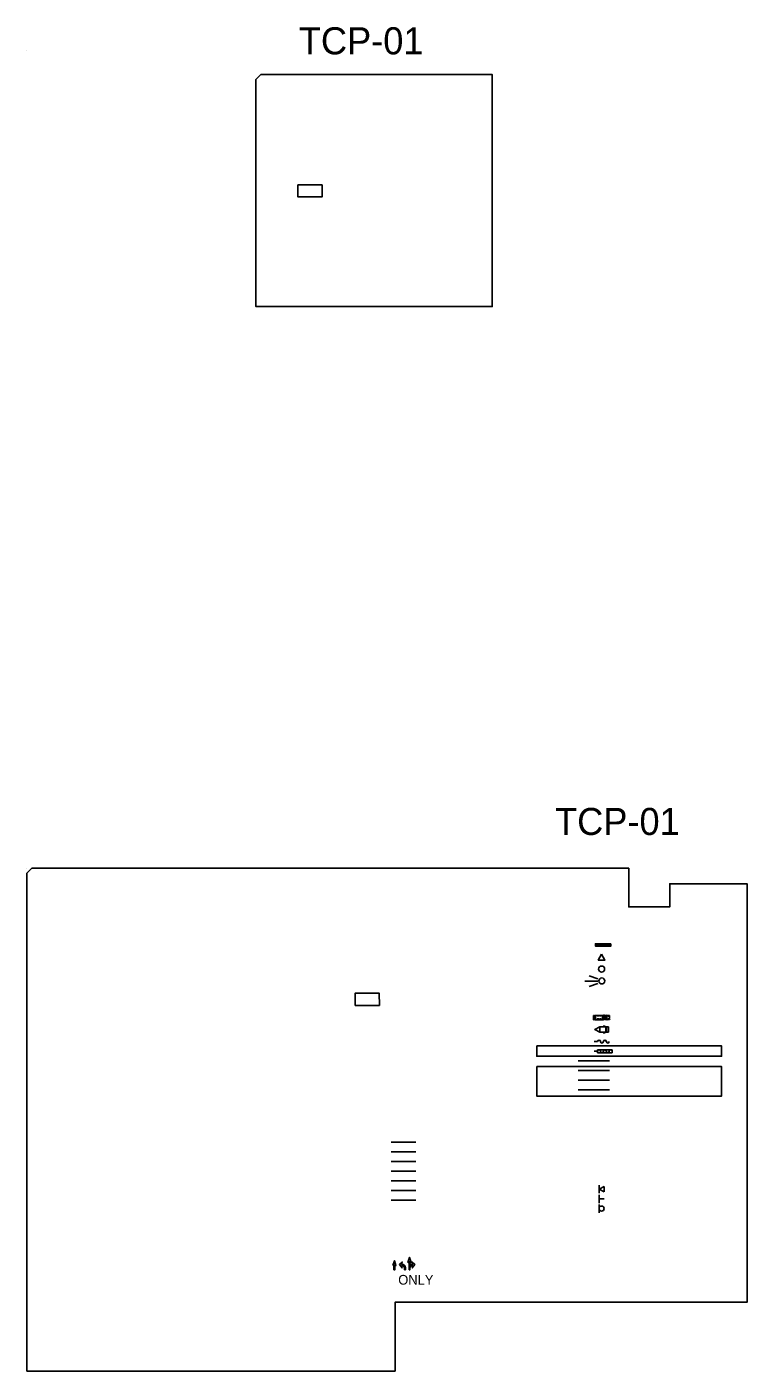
# Model space of a CAD drawing. Extents: x 2486454 to 2490507, y 369321 to 372999.
# Drawn here: x 2489017 to 2490507, y 370218 to 372999 of the extents above; entities that cross this region are included whole.
import ezdxf

# ---------------------------------------------------------------- set-up
doc = ezdxf.new("R2010")
doc.units = 0
for name, color, linetype in [('DEV BORDER CELL', 7, 'Continuous'), ('DEV CRASH CUSHION CELL', 7, 'Continuous'), ('Scratch_Level_3', 7, 'Continuous'), ('TC CONSTRUCTION PROPOSED ROADWAY SHADE', 7, 'Continuous'), ('TC DEV ATTENUATOR', 7, 'Continuous'), ('TC DEV ATTENUATOR TRUCK MOUNTED', 7, 'Continuous'), ('TC DEV BARRICADE', 7, 'Continuous'), ('TC DEV BARRIER PCB (ANCHORED)', 7, 'Continuous'), ('TC DEV BARRIER PCB (ANCHORED) RESET', 7, 'Continuous'), ('TC DEV BARRIER PCB (UN-ANCHORED)', 7, 'Continuous'), ('TC DEV BARRIER PCB (UN-ANCHORED) RESET', 7, 'Continuous'), ('TC DEV CMS', 7, 'Continuous'), ('TC DEV CONE', 7, 'Continuous'), ('TC DEV DRUM', 7, 'Continuous'), ('TC DEV SIGN', 7, 'Continuous'), ('TC DEV SIGN ARROW BOARD YELLOW', 7, 'Continuous'), ('TC PM CENTER DOUBLE 6 Y', 7, 'Continuous'), ('TC PM CHARACTER', 7, 'Continuous'), ('TC PM EDGELINE 6 W P6', 7, 'Continuous'), ('TC PM EDGELINE 6 Y P7', 7, 'Continuous'), ('TC PM GORELINE 12 W PS', 7, 'Continuous'), ('TC PM MINISKIP 3-9 6 W PK', 7, 'Continuous'), ('TC PM SKIP 6 W PJ', 7, 'Continuous'), ('TC PM STOP BAR 24 W P2', 7, 'Continuous'), ('TC PM SYMBOL', 7, 'Continuous'), ('TC SHEET LAYOUT SHAPE', 7, 'Continuous')]:
    doc.layers.add(name, color=color, linetype=linetype)

msp = doc.modelspace()

# ---------------------------------------------------------------- linework, layer by layer
at = {"layer": 'DEV BORDER CELL'}
for points in [[(2489627.4, 372671.9), (2489577.4, 372671.9), (2489577.4, 372646.9), (2489627.4, 372646.9)], [(2489745.7, 370999.8), (2489695.7, 370999.8), (2489695.8, 370974.8), (2489745.8, 370974.8)]]:
    msp.add_lwpolyline(points, close=True, dxfattribs=at)
at = {"layer": 'DEV CRASH CUSHION CELL'}
msp.add_line((2490189.8, 370879.8), (2490197.3, 370879.8), dxfattribs=at)
msp.add_lwpolyline([(2490197.3, 370882.8), (2490227.3, 370882.8), (2490227.3, 370876.8), (2490197.3, 370876.8)], close=True, dxfattribs=at)
for centre, start, end in [((2490200.3, 370879.8), 0, 180), ((2490212.3, 370879.8), 0, 180), ((2490224.3, 370879.8), 0, 180), ((2490206.3, 370879.8), 180, 0), ((2490218.3, 370879.8), 180, 0)]:
    msp.add_arc(centre, 3, start, end, dxfattribs=at)
at = {"layer": 'Scratch_Level_3'}
for p, q in [((2489016.6, 372950.1), (2489016.6, 372950.1)), ((2489016.6, 371258.3), (2489016.6, 371258.3))]:
    msp.add_line(p, q, dxfattribs=at)
for points in [[(2490071.4, 370890.8), (2490453.8, 370890.8), (2490453.8, 370869.7), (2490071.4, 370869.7)], [(2490071.4, 370848.2), (2490453.8, 370848.2), (2490453.8, 370787.2), (2490071.4, 370787.2)]]:
    msp.add_lwpolyline(points, close=True, dxfattribs=at)
at = {"layer": 'TC CONSTRUCTION PROPOSED ROADWAY SHADE'}
for points in [[(2489577.4, 372671.9), (2489627.4, 372671.9), (2489627.4, 372646.9), (2489577.4, 372646.9)], [(2489695.7, 370999.8), (2489745.7, 370999.8), (2489745.8, 370974.8), (2489695.8, 370974.8)]]:
    msp.add_lwpolyline(points, close=True, dxfattribs=at)
at = {"layer": 'TC DEV ATTENUATOR'}
msp.add_line((2490189.8, 370899.8), (2490197.3, 370899.8), dxfattribs=at)
for centre, radius, start, end in [((2490200.3, 370899.8), 3.03, 359.9999, 179.9999), ((2490206.3, 370899.8), 2.97, 179.9999, 359.9999), ((2490212.3, 370899.8), 3, 359.9999, 179.9999), ((2490218.3, 370899.8), 2.97, 179.9999, 359.9999)]:
    msp.add_arc(centre, radius, start, end, dxfattribs=at)
at = {"layer": 'TC DEV ATTENUATOR TRUCK MOUNTED'}
for p, q in [((2490188.8, 370945.2), (2490188.8, 370954.1)), ((2490188.8, 370954.1), (2490188.8, 370952.4)), ((2490188.8, 370954.1), (2490188.8, 370952.4)), ((2490188.8, 370954.1), (2490188.8, 370952.4)), ((2490188.8, 370954.1), (2490188.8, 370952.4)), ((2490188.8, 370952.4), (2490188.8, 370954.1)), ((2490188.8, 370954.1), (2490190.3, 370954.1)), ((2490190.3, 370954.1), (2490188.8, 370952.4)), ((2490188.8, 370951), (2490191.6, 370954.1)), ((2490192.8, 370954.1), (2490188.8, 370949.6)), ((2490188.8, 370949.6), (2490188.8, 370951)), ((2490188.8, 370949.6), (2490192.8, 370945.2)), ((2490188.8, 370948.3), (2490188.8, 370949.6)), ((2490191.6, 370945.2), (2490188.8, 370948.3)), ((2490188.8, 370946.9), (2490188.8, 370945.2)), ((2490190.3, 370945.2), (2490188.8, 370946.9)), ((2490188.8, 370945.2), (2490190.3, 370945.2)), ((2490190.1, 370949.6), (2490192.8, 370952.7)), ((2490192.8, 370946.6), (2490190.1, 370949.6)), ((2490192.8, 370951.3), (2490191.3, 370949.6)), ((2490191.3, 370949.6), (2490192.8, 370948)), ((2490191.6, 370954.1), (2490192.8, 370954.1)), ((2490192.8, 370945.2), (2490191.6, 370945.2)), ((2490192.7, 370954.1), (2490209.3, 370954.1)), ((2490192.8, 370945.2), (2490192.8, 370954.1)), ((2490192.8, 370952.7), (2490192.8, 370951.3)), ((2490192.8, 370948), (2490192.8, 370946.6)), ((2490192.8, 370945.2), (2490209.4, 370945.2)), ((2490196.1, 370954.1), (2490196.1, 370952.8)), ((2490196.1, 370952.8), (2490199.9, 370952.8)), ((2490196.1, 370946.6), (2490199.9, 370946.6)), ((2490196.1, 370946.6), (2490196.1, 370945.2)), ((2490199.9, 370954.1), (2490199.9, 370952.8)), ((2490199.9, 370946.6), (2490199.9, 370945.2)), ((2490201.1, 370954.2), (2490201.1, 370952.8)), ((2490201.1, 370952.8), (2490204.8, 370952.8)), ((2490201.1, 370946.6), (2490204.8, 370946.6)), ((2490201.1, 370946.6), (2490201.1, 370945.2)), ((2490204.8, 370954.2), (2490204.8, 370952.8)), ((2490204.8, 370946.6), (2490204.8, 370945.2)), ((2490207.1, 370954.1), (2490207.1, 370945.2)), ((2490209.3, 370954.1), (2490209.4, 370945.2)), ((2490211.9, 370954.1), (2490214.1, 370954.3)), ((2490211.9, 370945.5), (2490214.4, 370945.2)), ((2490216.1, 370953.5), (2490214.1, 370954.3)), ((2490216.3, 370945.8), (2490214.4, 370945.2)), ((2490216.1, 370953.6), (2490216.3, 370945.8)), ((2490216.1, 370953.5), (2490222, 370951.9)), ((2490216.3, 370945.8), (2490222.1, 370947.4)), ((2490222, 370951.9), (2490222.1, 370947.4))]:
    msp.add_line(p, q, dxfattribs=at)
for centre, radius, start, end in [((2490197.2, 370949.7), 15.3, 343.8365, 16.7472), ((2490205.8, 370949.5), 9.52, 333.4445, 30.0214), ((2490220.5, 370952.7), 1.61, 331.8365, 28.0763), ((2490220.7, 370946.6), 1.61, 331.8365, 28.0763)]:
    msp.add_arc(centre, radius, start, end, dxfattribs=at)
for centre, major_axis, ratio, start_param, end_param in [((2490210.6, 370954.1), (1.27, 0), 0.269913, 0, 3.141593), ((2490210.7, 370945.5), (1.26, 0), 0.27366, 3.141593, 6.283185), ((2490219, 370953.5), (2.91, -0.04), 0.2034, 0, 3.141593), ((2490219.2, 370945.8), (2.91, 0.03), 0.2034, 3.141593, 6.283185)]:
    msp.add_ellipse(centre, major_axis=major_axis, ratio=ratio, start_param=start_param, end_param=end_param, dxfattribs=at)
at = {"layer": 'TC DEV BARRICADE'}
for p, q in [((2490196.8, 371102.3), (2490192.8, 371097.3)), ((2490192.8, 371097.3), (2490192.8, 371102.3)), ((2490192.8, 371102.3), (2490192.8, 371102.3)), ((2490192.8, 371102.3), (2490196.8, 371102.3)), ((2490200.8, 371102.3), (2490196.6, 371097.3)), ((2490196.6, 371097.3), (2490200.8, 371097.3)), ((2490200.8, 371097.3), (2490200.8, 371102.3)), ((2490200.8, 371102.3), (2490200.8, 371102.3)), ((2490204.8, 371102.3), (2490200.8, 371097.3)), ((2490200.8, 371097.3), (2490200.8, 371102.3)), ((2490200.8, 371102.3), (2490200.8, 371102.3)), ((2490200.8, 371102.3), (2490204.8, 371102.3)), ((2490208.8, 371102.3), (2490204.6, 371097.3)), ((2490204.6, 371097.3), (2490208.8, 371097.3)), ((2490208.8, 371097.3), (2490208.8, 371102.3)), ((2490208.8, 371102.3), (2490208.8, 371102.3)), ((2490212.8, 371102.3), (2490208.8, 371097.3)), ((2490208.8, 371097.3), (2490208.8, 371102.3)), ((2490208.8, 371102.3), (2490208.8, 371102.3)), ((2490208.8, 371102.3), (2490212.8, 371102.3)), ((2490216.8, 371102.3), (2490212.6, 371097.3)), ((2490212.6, 371097.3), (2490216.8, 371097.3)), ((2490216.8, 371097.3), (2490216.8, 371102.3)), ((2490216.8, 371102.3), (2490216.8, 371102.3)), ((2490220.8, 371102.3), (2490216.8, 371097.3)), ((2490216.8, 371097.3), (2490216.8, 371102.3)), ((2490216.8, 371102.3), (2490216.8, 371102.3)), ((2490216.8, 371102.3), (2490220.8, 371102.3)), ((2490224.8, 371102.3), (2490220.6, 371097.3)), ((2490220.6, 371097.3), (2490224.8, 371097.3)), ((2490224.8, 371097.3), (2490224.8, 371102.3)), ((2490224.8, 371102.3), (2490224.8, 371102.3))]:
    msp.add_line(p, q, dxfattribs=at)
for points in [[(2490200.8, 371102.3), (2490196.6, 371097.3), (2490192.8, 371097.3), (2490196.8, 371102.3)], [(2490200.8, 371102.3), (2490200.8, 371097.3), (2490192.8, 371097.3), (2490192.8, 371102.3)], [(2490208.8, 371102.3), (2490204.6, 371097.3), (2490200.8, 371097.3), (2490204.8, 371102.3)], [(2490208.8, 371102.3), (2490208.8, 371097.3), (2490200.8, 371097.3), (2490200.8, 371102.3)], [(2490216.8, 371102.3), (2490212.6, 371097.3), (2490208.8, 371097.3), (2490212.8, 371102.3)], [(2490216.8, 371102.3), (2490216.8, 371097.3), (2490208.8, 371097.3), (2490208.8, 371102.3)], [(2490224.8, 371102.3), (2490220.6, 371097.3), (2490216.8, 371097.3), (2490220.8, 371102.3)], [(2490224.8, 371102.3), (2490224.8, 371097.3), (2490216.8, 371097.3), (2490216.8, 371102.3)]]:
    msp.add_lwpolyline(points, close=True, dxfattribs=at)
at = {"layer": 'TC DEV BARRIER PCB (ANCHORED)'}
msp.add_line((2490157, 370819.8), (2490222.1, 370819.8), dxfattribs=at)
at = {"layer": 'TC DEV BARRIER PCB (ANCHORED) RESET'}
msp.add_line((2490157, 370799.8), (2490222.1, 370799.8), dxfattribs=at)
at = {"layer": 'TC DEV BARRIER PCB (UN-ANCHORED)'}
msp.add_line((2490157, 370859.8), (2490222.1, 370859.8), dxfattribs=at)
at = {"layer": 'TC DEV BARRIER PCB (UN-ANCHORED) RESET'}
msp.add_line((2490157, 370839.8), (2490222.1, 370839.8), dxfattribs=at)
at = {"layer": 'TC DEV CMS'}
for p, q in [((2490201.7, 370930.6), (2490191.7, 370924.8)), ((2490201.7, 370919.1), (2490191.7, 370924.8)), ((2490219.5, 370930.7), (2490201.7, 370930.6)), ((2490201.7, 370930.6), (2490201.7, 370919.1)), ((2490219.6, 370919.1), (2490201.7, 370919.1)), ((2490212.8, 370931.9), (2490209.1, 370931.9)), ((2490212.8, 370930.9), (2490209.1, 370930.9)), ((2490212.8, 370918.8), (2490209.1, 370918.7)), ((2490212.8, 370917.7), (2490209.2, 370917.7)), ((2490214.4, 370930.7), (2490214.4, 370919.1)), ((2490215.4, 370930.7), (2490215.4, 370919.1)), ((2490215.4, 370930.7), (2490215.4, 370919.1)), ((2490219.5, 370930.7), (2490219.6, 370919.1)), ((2490219.6, 370919.1), (2490219.5, 370930.7))]:
    msp.add_line(p, q, dxfattribs=at)
msp.add_circle((2490191.6, 370924.9), 0.102, dxfattribs=at)
for centre, start, end in [((2490209.8, 370931.4), 142.1962, 218.0195), ((2490209.8, 370918.2), 142.1962, 218.0195), ((2490212.1, 370931.4), 322.1962, 38.0195), ((2490212.2, 370918.2), 322.1962, 38.0195)]:
    msp.add_arc(centre, 0.851, start, end, dxfattribs=at)
at = {"layer": 'TC DEV CONE'}
msp.add_lwpolyline([(2490205.5, 371081), (2490198.7, 371068.5), (2490212.4, 371068.5)], close=True, dxfattribs=at)
at = {"layer": 'TC DEV DRUM'}
msp.add_circle((2490205.6, 371049.8), 6.25, dxfattribs=at)
msp.add_circle((2490205.6, 371049.8), 6.25, dxfattribs=at)
at = {"layer": 'TC DEV SIGN'}
for p, q in [((2490200.3, 370583), (2490200.3, 370566)), ((2490200.7, 370603), (2490200.7, 370586)), ((2490200.7, 370594.5), (2490210.5, 370600.1)), ((2490210.5, 370588.9), (2490200.7, 370594.5)), ((2490210.5, 370600.1), (2490210.5, 370588.9)), ((2490200.3, 370574.5), (2490210.8, 370574.5)), ((2490200.3, 370563), (2490200.3, 370546))]:
    msp.add_line(p, q, dxfattribs=at)
msp.add_circle((2490205.6, 370554.5), 5.26, dxfattribs=at)
at = {"layer": 'TC DEV SIGN ARROW BOARD YELLOW'}
for p, q in [((2490197.6, 371024.9), (2490171, 371024.9)), ((2490197.6, 371029.5), (2490179.5, 371036.1)), ((2490197.6, 371020.3), (2490179.5, 371013.7))]:
    msp.add_line(p, q, dxfattribs=at)
msp.add_circle((2490206, 371025.3), 6.25, dxfattribs=at)
at = {"layer": 'TC PM CENTER DOUBLE 6 Y'}
msp.add_line((2489770.5, 370611.7), (2489821.2, 370611.7), dxfattribs=at)
at = {"layer": 'TC PM EDGELINE 6 W P6'}
msp.add_line((2489770.5, 370691.7), (2489821.2, 370691.7), dxfattribs=at)
at = {"layer": 'TC PM EDGELINE 6 Y P7'}
msp.add_line((2489770.5, 370671.7), (2489821.2, 370671.7), dxfattribs=at)
at = {"layer": 'TC PM GORELINE 12 W PS'}
msp.add_line((2489770.5, 370591.7), (2489821.2, 370591.7), dxfattribs=at)
at = {"layer": 'TC PM MINISKIP 3-9 6 W PK'}
msp.add_line((2489770.5, 370631.7), (2489821.2, 370631.7), dxfattribs=at)
at = {"layer": 'TC PM SKIP 6 W PJ'}
msp.add_line((2489770.5, 370651.7), (2489821.2, 370651.7), dxfattribs=at)
at = {"layer": 'TC PM STOP BAR 24 W P2'}
msp.add_line((2489770.5, 370571.7), (2489821.2, 370571.7), dxfattribs=at)
at = {"layer": 'TC PM SYMBOL'}
for points in [[(2489773.6, 370436.4), (2489775.8, 370438.4), (2489775.8, 370427.8), (2489777.8, 370427.8), (2489777.8, 370438.4), (2489779.9, 370436.4), (2489776.8, 370446.6)], [(2489773.6, 370436.4), (2489775.8, 370438.4), (2489775.8, 370427.8), (2489777.8, 370427.8), (2489777.8, 370438.4), (2489779.9, 370436.4), (2489776.8, 370446.6)], [(2489797.5, 370427.8), (2489799.5, 370427.8), (2489799.5, 370432.9), (2489799.4, 370433.9), (2489799.3, 370434.6), (2489799, 370435.4), (2489798.7, 370436.1), (2489798.3, 370436.6), (2489797.8, 370437.2), (2489797.3, 370437.7), (2489796.7, 370438.2), (2489795.9, 370438.6), (2489795.3, 370438.9), (2489794.4, 370439.1), (2489793.2, 370439.3), (2489791.6, 370439.3), (2489793, 370443.8), (2489787.3, 370438.6), (2489792.6, 370431.6), (2489791.6, 370436.1), (2489793, 370436.1), (2489793.7, 370436.1), (2489794.4, 370435.9), (2489794.9, 370435.6), (2489795.6, 370435.2), (2489796.1, 370434.8), (2489796.6, 370434.2), (2489797, 370433.4), (2489797.3, 370432.7), (2489797.5, 370431.6)], [(2489797.5, 370427.8), (2489799.5, 370427.8), (2489799.5, 370432.9), (2489799.4, 370433.9), (2489799.3, 370434.6), (2489799, 370435.4), (2489798.7, 370436.1), (2489798.3, 370436.6), (2489797.8, 370437.2), (2489797.3, 370437.7), (2489796.7, 370438.1), (2489795.9, 370438.6), (2489795.3, 370438.9), (2489794.4, 370439.1), (2489793.2, 370439.3), (2489791.6, 370439.3), (2489793, 370443.8), (2489787.3, 370438.6), (2489792.6, 370431.6), (2489791.6, 370436.1), (2489793, 370436.1), (2489793.7, 370436.1), (2489794.4, 370435.9), (2489794.9, 370435.6), (2489795.6, 370435.2), (2489796.1, 370434.8), (2489796.6, 370434.2), (2489797, 370433.4), (2489797.3, 370432.7), (2489797.5, 370431.6)], [(2489807.1, 370427.8), (2489807.1, 370445.1), (2489804.9, 370443.1), (2489808.1, 370453.3), (2489811.3, 370443.1), (2489809.1, 370445.1), (2489809.1, 370437.6), (2489810, 370438.3), (2489810.7, 370438.7), (2489811.6, 370439), (2489812.4, 370439.2), (2489813.3, 370439.3), (2489814.9, 370439.3), (2489813.6, 370443.8), (2489819.3, 370438.6), (2489813.9, 370431.6), (2489814.9, 370436.1), (2489813.6, 370436.1), (2489812.9, 370436.1), (2489812.1, 370435.9), (2489811.4, 370435.5), (2489810.8, 370435.1), (2489810.1, 370434.4), (2489809.6, 370433.6), (2489809.3, 370432.6), (2489809.1, 370431.6), (2489809.1, 370427.8)], [(2489807.1, 370427.8), (2489807.1, 370445.1), (2489804.9, 370443.1), (2489808.1, 370453.3), (2489811.3, 370443.1), (2489809.1, 370445.1), (2489809.1, 370437.6), (2489810, 370438.3), (2489810.7, 370438.7), (2489811.6, 370439), (2489812.4, 370439.2), (2489813.3, 370439.3), (2489814.9, 370439.3), (2489813.6, 370443.8), (2489819.3, 370438.6), (2489813.9, 370431.6), (2489814.9, 370436.1), (2489813.6, 370436.1), (2489812.9, 370436.1), (2489812.1, 370435.9), (2489811.4, 370435.5), (2489810.8, 370435.1), (2489810.1, 370434.4), (2489809.6, 370433.6), (2489809.3, 370432.6), (2489809.1, 370431.6), (2489809.1, 370427.8)]]:
    msp.add_lwpolyline(points, close=True, dxfattribs=at)
at = {"layer": 'TC SHEET LAYOUT SHAPE'}
for points in [[(2489490.5, 372889.9), (2489500.5, 372899.9), (2489979.3, 372899.9), (2489979.3, 372420.3), (2489490.5, 372420.3)], [(2489016.6, 370666.8), (2489016.6, 370976.2), (2489016.6, 371248.3), (2489026.6, 371258.3), (2489469.6, 371258.3), (2489940.6, 371258.3), (2490261.6, 371258.3), (2490261.6, 371178.3), (2490346.6, 371178.3), (2490346.6, 371226.3), (2490506.6, 371226.3), (2490506.6, 370891.3), (2490506.6, 370612.1), (2490506.6, 370360.8), (2489778.4, 370360.8), (2489778.4, 370218.3), (2489608.9, 370218.3), (2489256.1, 370218.3), (2489016.6, 370218.3)]]:
    msp.add_lwpolyline(points, close=True, dxfattribs=at)

# ---------------------------------------------------------------- texts
at = {"layer": 'TC PM CHARACTER'}
msp.add_text('ONLY', height=20, rotation=359.9999, dxfattribs=at).set_placement((2489784.8, 370397.2))
at = {"layer": 'TC SHEET LAYOUT SHAPE'}
for p in [(2489579.1, 372941.9), (2490109.2, 371327.2)]:
    msp.add_text('TCP-01', height=56, rotation=0.0001, dxfattribs=at).set_placement(p)

doc.saveas('drawing.dxf')
